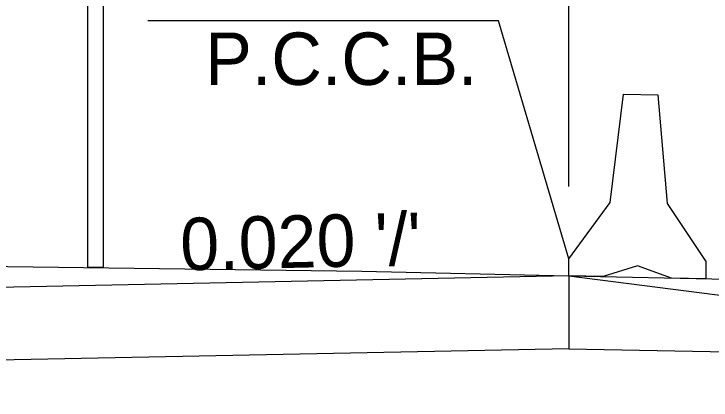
# Model space of a CAD drawing. Extents: x 1807779 to 1818251, y 673292 to 678849.
# Drawn here: x 1813411.4 to 1813507.2, y 676955.4 to 677008.5 of the extents above; entities that cross this region are included whole.
import ezdxf

# ---------------------------------------------------------------- set-up
doc = ezdxf.new("R2010")
doc.units = 0
for name, color, linetype in [('Default', 7, 'Continuous'), ('Dimensions', 7, 'Continuous'), ('EX_TERRAIN', 7, 'Continuous'), ('Level 1', 7, 'Continuous'), ('Vertical Panels', 7, 'Continuous')]:
    doc.layers.add(name, color=color, linetype=linetype)

msp = doc.modelspace()

# ---------------------------------------------------------------- linework, layer by layer
at = {"layer": 'Default'}
for p, q in [((1813487.671, 676972.485), (1813377.693, 676970.286)), ((1813487.671, 676972.485), (1813487.671, 676962.485)), ((1813487.671, 676972.485), (1813597.649, 676970.286)), ((1813487.671, 676962.485), (1813274.965, 676958.231)), ((1813487.671, 676962.485), (1813700.594, 676958.227))]:
    msp.add_line(p, q, dxfattribs=at)
at = {"layer": 'Dimensions'}
for p, q in [((1813487.671, 676984.764), (1813487.671, 677242.534)), ((1813421.531, 676980.157), (1813421.531, 677097.633))]:
    msp.add_line(p, q, dxfattribs=at)
msp.add_lwpolyline([(1813487.691, 676974.841), (1813478.005, 677007.523), (1813429.784, 677007.523)], dxfattribs=at)
at = {"layer": 'EX_TERRAIN'}
msp.add_lwpolyline([(1812678.819, 676968.885), (1812734.478, 676935.928), (1812877.87, 676880.694), (1812959.162, 676882.834), (1813053.738, 676934.265), (1813144.452, 676972.05), (1813219.029, 676974.199), (1813299.208, 676975.268), (1813459.204, 676973.129), (1813487.671, 676972.485), (1813516.003, 676968.904), (1813566.565, 676954.47), (1813614.025, 676941.377), (1813728.731, 676880.366), (1813806.181, 676862.533), (1813861.672, 676857.875), (1813918.121, 676853.044), (1814104.928, 676852.066), (1814246.727, 676850.15)], dxfattribs=at)
at = {"layer": 'Level 1'}
for p, q in [((1813493.345, 676982.583), (1813495.213, 676997.471)), ((1813495.213, 676997.471), (1813499.925, 676997.377)), ((1813499.925, 676997.377), (1813501.197, 676982.426)), ((1813487.691, 676974.841), (1813493.345, 676982.583)), ((1813501.197, 676982.426), (1813506.536, 676974.464)), ((1813487.671, 676972.485), (1813487.691, 676974.841)), ((1813506.536, 676974.464), (1813506.515, 676972.108)), ((1813497.124, 676973.867), (1813492.382, 676972.391)), ((1813501.804, 676972.203), (1813497.124, 676973.867)), ((1813492.382, 676972.391), (1813487.671, 676972.485)), ((1813506.515, 676972.108), (1813501.804, 676972.203))]:
    msp.add_line(p, q, dxfattribs=at)
at = {"layer": 'Vertical Panels'}
msp.add_lwpolyline([(1813421.531, 677022.174), (1813423.641, 677022.174), (1813423.641, 676973.633), (1813421.531, 676973.633)], close=True, dxfattribs=at)

# ---------------------------------------------------------------- texts
at = {"layer": 'Dimensions'}
msp.add_text('P.C.C.B.', height=7.2, dxfattribs=at).set_placement((1813437.665, 676998.724))
msp.add_text("0.020 '/'", height=7.2, rotation=1.31686, dxfattribs=at).set_placement((1813434.325, 676973.243))

doc.saveas('drawing.dxf')
